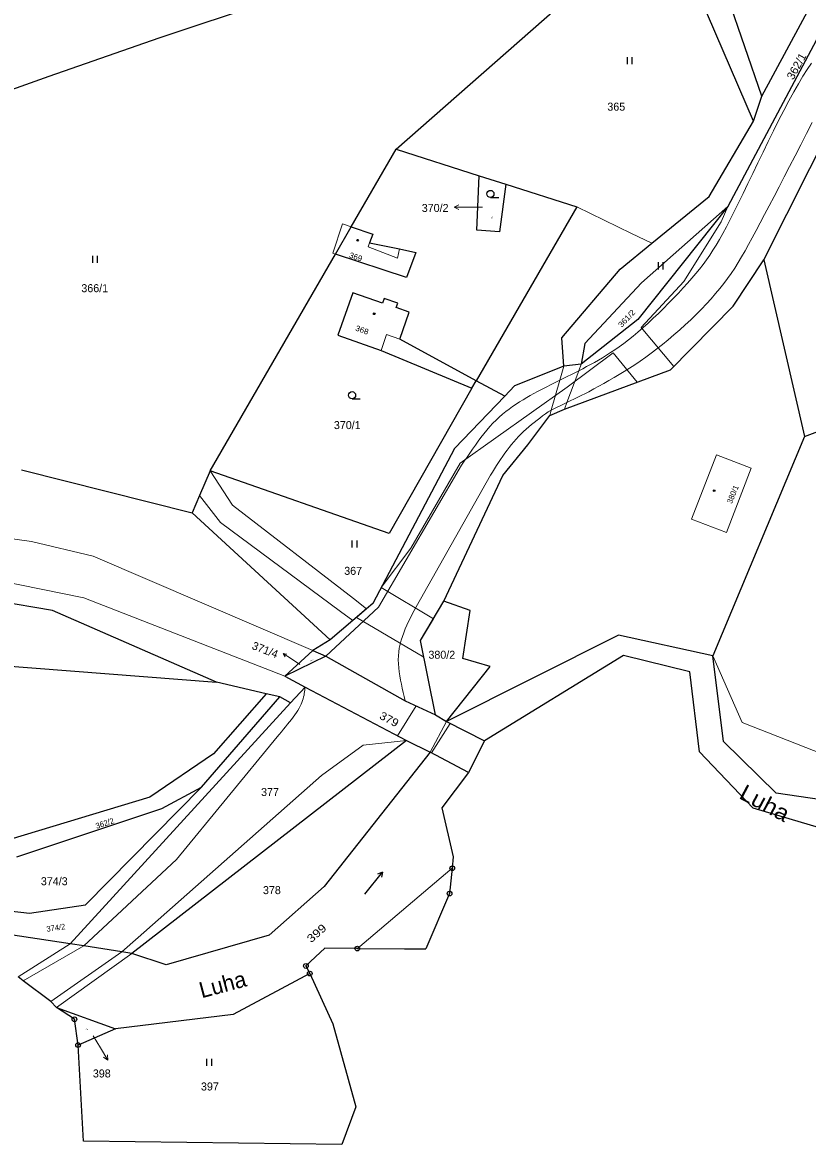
# Model space of a CAD drawing. Extents: x -504006 to -501322, y -1128098 to -1124665.
# Drawn here: x -502418.6 to -502251.7, y -1128098 to -1127859.7 of the extents above; entities that cross this region are included whole.
import ezdxf
from ezdxf.enums import TextEntityAlignment as Align

# ---------------------------------------------------------------- set-up
doc = ezdxf.new("R2010")
doc.units = 0
doc.header["$LTSCALE"] = 0.68
for name, color, linetype, lineweight in [('1', 7, 'Continuous', 25), ('13', 7, 'Continuous', 13), ('3', 7, 'Continuous', 25), ('4', 7, 'Continuous', 13), ('5', 7, 'Continuous', 25), ('7', 7, 'Continuous', 13), ('8', 7, 'Continuous', 25)]:
    doc.layers.add(name, color=color, linetype=linetype, lineweight=lineweight)
doc.layers.add('2', color=7, linetype='Continuous')

msp = doc.modelspace()

# ---------------------------------------------------------------- linework, layer by layer
at = {"layer": '1'}
for p, q in [((-502261.45, -1127875.35), (-502289.09, -1127795.08)), ((-502339.14, -1127886.6), (-502282.17, -1127836.5)), ((-502263.24, -1127880.61), (-502282.17, -1127836.5)), ((-502366.78, -1127855.42), (-502389.61, -1127863.03)), ((-502261.45, -1127875.35), (-502250.3, -1127854.66)), ((-502246.89, -1127857.93), (-502268.68, -1127898.79)), ((-502389.61, -1127863.03), (-502412.95, -1127871.18)), ((-502412.95, -1127871.18), (-502437.29, -1127879.78)), ((-502263.24, -1127880.61), (-502261.45, -1127875.35)), ((-502261.01, -1127910.1), (-502243.76, -1127875.74)), ((-502272.61, -1127896.66), (-502263.24, -1127880.61)), ((-502348.68, -1127903.07), (-502339.14, -1127886.6)), ((-502339.14, -1127886.6), (-502321.51, -1127892.23)), ((-502321.98, -1127903.78), (-502321.51, -1127892.23)), ((-502321.51, -1127892.23), (-502315.88, -1127894.03)), ((-502315.88, -1127894.03), (-502317.2, -1127904.16)), ((-502315.88, -1127894.03), (-502300.78, -1127898.86)), ((-502300.78, -1127898.86), (-502322.17, -1127935.76)), ((-502268.68, -1127898.79), (-502287.79, -1127922.8)), ((-502268.68, -1127898.79), (-502287.04, -1127914.99)), ((-502284.8, -1127906.58), (-502272.61, -1127896.66)), ((-502352.06, -1127908.9), (-502348.68, -1127903.07)), ((-502348.68, -1127903.07), (-502344.08, -1127904.66)), ((-502344.08, -1127904.66), (-502344.78, -1127906.51)), ((-502317.2, -1127904.16), (-502321.98, -1127903.78)), ((-502344.78, -1127906.51), (-502338.41, -1127907.77)), ((-502338.41, -1127907.77), (-502334.98, -1127908.5)), ((-502291.56, -1127912.08), (-502284.8, -1127906.58)), ((-502378.69, -1127954.88), (-502352.06, -1127908.9)), ((-502336.96, -1127913.85), (-502352.06, -1127908.9)), ((-502334.98, -1127908.5), (-502336.96, -1127913.85)), ((-502267.52, -1127919.9), (-502261.01, -1127910.1)), ((-502261.01, -1127910.1), (-502252.35, -1127947.59)), ((-502303.93, -1127926.63), (-502291.56, -1127912.08)), ((-502287.04, -1127914.99), (-502299.07, -1127927.86)), ((-502348.37, -1127917.07), (-502351.55, -1127926.1)), ((-502342.03, -1127919.31), (-502348.37, -1127917.07)), ((-502341.67, -1127918.29), (-502342.03, -1127919.31)), ((-502338.79, -1127919.31), (-502341.67, -1127918.29)), ((-502339.12, -1127920.25), (-502338.79, -1127919.31)), ((-502336.37, -1127921.22), (-502339.12, -1127920.25)), ((-502280.84, -1127933.48), (-502267.52, -1127919.9)), ((-502338.39, -1127926.96), (-502336.37, -1127921.22)), ((-502287.79, -1127922.8), (-502299.81, -1127932.26)), ((-502351.55, -1127926.1), (-502342.36, -1127929.34)), ((-502322.17, -1127935.76), (-502338.39, -1127926.96)), ((-502303.53, -1127932.65), (-502303.93, -1127926.63)), ((-502342.36, -1127929.34), (-502323.05, -1127937.35)), ((-502299.07, -1127927.86), (-502299.81, -1127932.26)), ((-502299.81, -1127932.26), (-502303.53, -1127932.65)), ((-502303.53, -1127932.65), (-502313.98, -1127936.85)), ((-502303.4, -1127941.78), (-502280.84, -1127933.48)), ((-502323.05, -1127937.35), (-502322.17, -1127935.76)), ((-502316.09, -1127939.05), (-502322.17, -1127935.76)), ((-502313.98, -1127936.85), (-502316.09, -1127939.05)), ((-502323.05, -1127937.35), (-502340.61, -1127968.24)), ((-502316.09, -1127939.05), (-502326.73, -1127950.16)), ((-502306.52, -1127943.16), (-502303.4, -1127941.78)), ((-502311.14, -1127949.39), (-502306.52, -1127943.16)), ((-502252.35, -1127947.59), (-502241.62, -1127943.56)), ((-502252.35, -1127947.59), (-502271.89, -1127994.18)), ((-502326.73, -1127950.16), (-502344.12, -1127983.08)), ((-502316.48, -1127955.93), (-502311.14, -1127949.39)), ((-502418.74, -1127954.72), (-502382.52, -1127963.86)), ((-502378.69, -1127954.88), (-502380.96, -1127960.17)), ((-502340.61, -1127968.24), (-502378.69, -1127954.88)), ((-502329, -1127982.59), (-502316.48, -1127955.93)), ((-502380.96, -1127960.17), (-502382.52, -1127963.86)), ((-502353.18, -1127990.79), (-502382.52, -1127963.86)), ((-502412.17, -1127984.56), (-502441.15, -1127979.72)), ((-502377.31, -1127999.77), (-502412.17, -1127984.56)), ((-502345.44, -1127984.21), (-502348.38, -1127986.7)), ((-502344.12, -1127983.08), (-502345.44, -1127984.21)), ((-502333.98, -1127990.98), (-502329, -1127982.59)), ((-502323.4, -1127984.6), (-502329, -1127982.59)), ((-502325, -1127994.8), (-502323.4, -1127984.6)), ((-502348.38, -1127986.7), (-502353.18, -1127990.79)), ((-502525.02, -1127988.48), (-502377.31, -1127999.77)), ((-502353.18, -1127990.79), (-502356.83, -1127993.06)), ((-502330.8, -1128006.76), (-502333.98, -1127990.98)), ((-502291.92, -1127989.81), (-502328.44, -1128008.18)), ((-502271.89, -1127994.18), (-502291.92, -1127989.81)), ((-502356.83, -1127993.06), (-502362.84, -1127998.54)), ((-502356.83, -1127993.06), (-502354.12, -1127994.27)), ((-502290.84, -1127994.17), (-502320.37, -1128012.27)), ((-502276.73, -1127997.64), (-502290.84, -1127994.17)), ((-502269.62, -1128012.41), (-502271.89, -1127994.18)), ((-502354.12, -1127994.27), (-502362.84, -1127998.54)), ((-502354.12, -1127994.27), (-502337.21, -1128003.75)), ((-502328.44, -1128008.18), (-502319.2, -1127996.5)), ((-502319.2, -1127996.5), (-502325, -1127994.8)), ((-502362.84, -1127998.54), (-502358.49, -1128000.84)), ((-502274.68, -1128014.62), (-502276.73, -1127997.64)), ((-502366.78, -1128002.26), (-502377.31, -1127999.77)), ((-502358.49, -1128000.84), (-502361.59, -1128004.22)), ((-502358.49, -1128000.84), (-502336.97, -1128012.2)), ((-502380.49, -1128022.11), (-502363.86, -1128002.95)), ((-502366.78, -1128002.26), (-502377.97, -1128015.05)), ((-502363.86, -1128002.95), (-502366.78, -1128002.26)), ((-502361.59, -1128004.22), (-502363.86, -1128002.95)), ((-502337.21, -1128003.75), (-502330.8, -1128006.76)), ((-502408.4, -1128055.35), (-502361.59, -1128004.22)), ((-502330.8, -1128006.76), (-502328.44, -1128008.18)), ((-502328.44, -1128008.18), (-502320.37, -1128012.27)), ((-502336.97, -1128012.2), (-502395.31, -1128057.42)), ((-502336.97, -1128012.2), (-502331.93, -1128014.67)), ((-502320.37, -1128012.27), (-502323.77, -1128018.99)), ((-502258.41, -1128023.41), (-502269.62, -1128012.41)), ((-502377.97, -1128015.05), (-502391.5, -1128024.2)), ((-502331.93, -1128014.67), (-502354.43, -1128043.24)), ((-502323.77, -1128018.99), (-502331.93, -1128014.67)), ((-502263.31, -1128026.56), (-502274.68, -1128014.62)), ((-502405.15, -1128047.13), (-502380.49, -1128022.11)), ((-502388.93, -1128026.65), (-502380.49, -1128022.11)), ((-502391.5, -1128024.2), (-502421.24, -1128033.24)), ((-502245.25, -1128025.33), (-502258.41, -1128023.41)), ((-502419.75, -1128036.93), (-502388.93, -1128026.65)), ((-502249.21, -1128030.75), (-502263.31, -1128026.56)), ((-502327.02, -1128036.92), (-502327.23, -1128039.33)), ((-502327.23, -1128039.33), (-502327.81, -1128044.72)), ((-502354.43, -1128043.24), (-502366.1, -1128053.55)), ((-502441.79, -1128046.07), (-502417.05, -1128048.89)), ((-502327.81, -1128044.72), (-502332.83, -1128056.43)), ((-502417.05, -1128048.89), (-502405.15, -1128047.13)), ((-502408.4, -1128055.35), (-502442.74, -1128050.19)), ((-502366.1, -1128053.55), (-502387.99, -1128059.81)), ((-502405.52, -1128055.8), (-502408.4, -1128055.35)), ((-502397.45, -1128057.08), (-502405.52, -1128055.8)), ((-502395.31, -1128057.42), (-502397.45, -1128057.08)), ((-502387.99, -1128059.81), (-502395.31, -1128057.42)), ((-502354.33, -1128056.27), (-502358.33, -1128060.09)), ((-502347.4, -1128056.4), (-502354.33, -1128056.27)), ((-502347.4, -1128056.4), (-502337.4, -1128056.44)), ((-502337.4, -1128056.44), (-502332.83, -1128056.43)), ((-502358.33, -1128060.09), (-502357.51, -1128061.7)), ((-502418.39, -1128063.21), (-502419.47, -1128062.4)), ((-502412.52, -1128067.62), (-502418.39, -1128063.21)), ((-502357.51, -1128061.7), (-502373.81, -1128070.41)), ((-502357.51, -1128061.7), (-502352.6, -1128072.39)), ((-502411.31, -1128068.88), (-502412.52, -1128067.62)), ((-502407.51, -1128071.41), (-502411.31, -1128068.88)), ((-502411.31, -1128068.88), (-502398.76, -1128073.44)), ((-502373.81, -1128070.41), (-502398.76, -1128073.44)), ((-502406.74, -1128076.89), (-502407.51, -1128071.41)), ((-502352.6, -1128072.39), (-502347.69, -1128089.99)), ((-502398.76, -1128073.44), (-502406.74, -1128076.89)), ((-502405.59, -1128097.3), (-502406.74, -1128076.89)), ((-502347.69, -1128089.99), (-502350.71, -1128098.02)), ((-502350.71, -1128098.02), (-502405.59, -1128097.3))]:
    msp.add_line(p, q, dxfattribs=at)
msp.add_lwpolyline([(-502323.77, -1128018.99), (-502329.42, -1128026.51), (-502327.02, -1128036.92)], dxfattribs=at)
at = {"layer": '13'}
for points in [[(-502268.68, -1127898.79), (-502287.79, -1127922.8), (-502299.81, -1127932.26), (-502303.53, -1127932.65), (-502313.98, -1127936.85), (-502316.09, -1127939.05), (-502326.73, -1127950.16), (-502342.35, -1127979.72), (-502336.01, -1127971.33), (-502325.56, -1127953.28), (-502302.83, -1127937.15), (-502293.06, -1127929.85), (-502287.94, -1127936.09), (-502280.84, -1127933.48), (-502280.14, -1127932.77), (-502287.06, -1127924.45), (-502278, -1127914.68), (-502270.12, -1127902)], [(-502344.12, -1127983.08), (-502345.44, -1127984.21), (-502347.59, -1127986.03), (-502333.27, -1127994.52), (-502333.98, -1127990.98), (-502331.21, -1127986.32), (-502342.35, -1127979.72)], [(-502334.88, -1128004.84), (-502338.9, -1128011.18), (-502336.97, -1128012.2), (-502334.07, -1128013.62), (-502331.93, -1128014.67), (-502331.62, -1128014.84), (-502327.65, -1128008.58), (-502328.44, -1128008.18), (-502330.8, -1128006.76)]]:
    msp.add_lwpolyline(points, close=True, dxfattribs=at)
at = {"layer": '3'}
for p, q in [((-502289.991, -1127868.51), (-502289.991, -1127867.01)), ((-502288.99, -1127868.51), (-502288.99, -1127867.01)), ((-502319.113, -1127896.83), (-502317.363, -1127896.83)), ((-502403.611, -1127910.75), (-502403.611, -1127909.25)), ((-502402.61, -1127910.75), (-502402.61, -1127909.25)), ((-502283.421, -1127912.11), (-502283.421, -1127910.61)), ((-502282.42, -1127912.11), (-502282.42, -1127910.61)), ((-502348.513, -1127939.59), (-502346.763, -1127939.59)), ((-502348.471, -1127971.19), (-502348.471, -1127969.69)), ((-502347.47, -1127971.19), (-502347.47, -1127969.69)), ((-502342.086, -1128040.138), (-502342.292, -1128041.216)), ((-502379.351, -1128081.3), (-502379.351, -1128079.8)), ((-502378.35, -1128081.3), (-502378.35, -1128079.8))]:
    msp.add_line(p, q, dxfattribs=at)
msp.add_lwpolyline([(-502345.78, -1128044.866), (-502342.086, -1128040.138), (-502343.082, -1128040.599)], dxfattribs=at)
for centre in [(-502319.1129, -1127896.0798), (-502348.5129, -1127938.8398)]:
    msp.add_circle(centre, 0.75, dxfattribs=at)
at = {"layer": '4'}
for p, q in [((-502300.78, -1127898.86), (-502289.13, -1127904.49)), ((-502352.63, -1127908.71), (-502350.54, -1127902.42)), ((-502350.54, -1127902.42), (-502348.68, -1127903.07)), ((-502289.13, -1127904.49), (-502284.8, -1127906.58)), ((-502344.78, -1127906.51), (-502345.11, -1127907.34)), ((-502345.11, -1127907.34), (-502338.83, -1127909.73)), ((-502338.83, -1127909.73), (-502338.41, -1127907.77)), ((-502352.06, -1127908.9), (-502352.63, -1127908.71)), ((-502341.17, -1127925.98), (-502342.36, -1127929.34)), ((-502338.39, -1127926.96), (-502341.17, -1127925.98)), ((-502299.81, -1127932.26), (-502300.33, -1127933.65)), ((-502303.53, -1127932.65), (-502304.39, -1127935.67)), ((-502304.39, -1127935.67), (-502300.33, -1127933.65)), ((-502300.33, -1127933.65), (-502302.88, -1127940.41)), ((-502300.33, -1127933.65), (-502299.49, -1127933.23)), ((-502309.12, -1127938.03), (-502304.39, -1127935.67)), ((-502304.39, -1127935.67), (-502306.2, -1127942.05)), ((-502298.21, -1127938.1), (-502302.88, -1127940.41)), ((-502302.88, -1127940.41), (-502306.2, -1127942.05)), ((-502302.88, -1127940.41), (-502303.4, -1127941.78)), ((-502306.2, -1127942.05), (-502306.86, -1127942.37)), ((-502306.2, -1127942.05), (-502306.52, -1127943.16)), ((-502342.9, -1127983.87), (-502325.24, -1127953.72)), ((-502276.37, -1127965.15), (-502271.06, -1127951.48)), ((-502271.06, -1127951.48), (-502263.68, -1127954.34)), ((-502378.69, -1127954.88), (-502373.93, -1127962.17)), ((-502319.11, -1127955.84), (-502334.89, -1127983.77)), ((-502263.68, -1127954.34), (-502268.98, -1127968.01)), ((-502376.49, -1127965.86), (-502380.96, -1127960.17)), ((-502373.93, -1127962.17), (-502348.22, -1127982.06)), ((-502268.98, -1127968.01), (-502276.37, -1127965.15)), ((-502351.01, -1127984.76), (-502376.49, -1127965.86)), ((-502428.27, -1127968.36), (-502416.65, -1127969.89)), ((-502416.65, -1127969.89), (-502403.51, -1127973.03)), ((-502403.51, -1127973.03), (-502356.83, -1127993.06)), ((-502405.51, -1127981.89), (-502431.19, -1127976.74)), ((-502362.84, -1127998.54), (-502405.51, -1127981.89)), ((-502348.22, -1127982.06), (-502345.44, -1127984.21)), ((-502354.12, -1127994.27), (-502342.9, -1127983.87)), ((-502348.38, -1127986.7), (-502351.01, -1127984.76)), ((-502271.89, -1127994.18), (-502265.62, -1128008.38)), ((-502328.44, -1128008.18), (-502331.93, -1128014.67)), ((-502265.62, -1128008.38), (-502244.31, -1128016.77)), ((-502364.47, -1128011.42), (-502385.8, -1128037.46)), ((-502346.16, -1128013.18), (-502355.03, -1128019.61)), ((-502336.97, -1128012.2), (-502346.16, -1128013.18)), ((-502355.03, -1128019.61), (-502393.97, -1128054.01)), ((-502385.8, -1128037.46), (-502398.47, -1128049.24)), ((-502347.4, -1128056.4), (-502327.23, -1128039.33)), ((-502398.47, -1128049.24), (-502405.52, -1128055.8)), ((-502408.4, -1128055.35), (-502419.47, -1128062.4)), ((-502418.39, -1128063.21), (-502405.52, -1128055.8)), ((-502393.97, -1128054.01), (-502397.45, -1128057.08)), ((-502397.45, -1128057.08), (-502412.52, -1128067.62)), ((-502411.31, -1128068.88), (-502395.31, -1128057.42))]:
    msp.add_line(p, q, dxfattribs=at)
for points in [[(-502299.49, -1127933.23), (-502298.669, -1127932.784), (-502297.836, -1127932.328), (-502297.007, -1127931.866), (-502296.169, -1127931.388), (-502295.311, -1127930.882), (-502294.448, -1127930.355), (-502293.569, -1127929.795), (-502292.659, -1127929.19), (-502291.738, -1127928.549), (-502290.791, -1127927.858), (-502289.805, -1127927.105), (-502288.8, -1127926.3), (-502287.763, -1127925.433), (-502286.688, -1127924.497), (-502285.607, -1127923.525), (-502284.516, -1127922.513), (-502283.41, -1127921.458), (-502282.322, -1127920.394), (-502281.248, -1127919.316), (-502280.181, -1127918.22), (-502279.156, -1127917.141), (-502278.168, -1127916.074), (-502277.212, -1127915.016), (-502276.32, -1127914), (-502275.485, -1127913.018), (-502274.69, -1127912.046), (-502273.943, -1127911.09), (-502273.227, -1127910.121), (-502272.521, -1127909.11), (-502271.832, -1127908.065), (-502271.142, -1127906.956), (-502270.432, -1127905.752), (-502269.709, -1127904.465), (-502268.955, -1127903.064), (-502268.149, -1127901.512), (-502267.3, -1127899.83), (-502266.392, -1127897.99), (-502265.419, -1127895.988), (-502264.412, -1127893.898), (-502263.369, -1127891.723), (-502262.284, -1127889.464), (-502261.193, -1127887.201), (-502260.09, -1127884.935), (-502258.971, -1127882.664), (-502257.872, -1127880.472), (-502256.786, -1127878.356), (-502255.711, -1127876.32), (-502254.68, -1127874.44), (-502253.687, -1127872.711), (-502252.718, -1127871.108), (-502251.795, -1127869.657), (-502250.901, -1127868.323)], [(-502250.744, -1127880.895), (-502251.966, -1127883.277), (-502253.174, -1127885.63), (-502254.377, -1127887.97), (-502255.541, -1127890.233), (-502256.677, -1127892.435), (-502257.793, -1127894.593), (-502258.856, -1127896.644), (-502259.877, -1127898.606), (-502260.861, -1127900.489), (-502261.78, -1127902.24), (-502262.644, -1127903.874), (-502263.471, -1127905.418), (-502264.25, -1127906.846), (-502265.001, -1127908.188), (-502265.744, -1127909.472), (-502266.471, -1127910.677), (-502267.2, -1127911.832), (-502267.951, -1127912.96), (-502268.716, -1127914.048), (-502269.514, -1127915.118), (-502270.366, -1127916.197), (-502271.26, -1127917.27), (-502272.214, -1127918.358), (-502273.237, -1127919.472), (-502274.297, -1127920.579), (-502275.4, -1127921.688), (-502276.551, -1127922.804), (-502277.717, -1127923.897), (-502278.905, -1127924.973), (-502280.121, -1127926.04), (-502281.331, -1127927.066), (-502282.541, -1127928.059), (-502283.759, -1127929.023), (-502284.95, -1127929.93), (-502286.122, -1127930.788), (-502287.289, -1127931.609), (-502288.425, -1127932.377), (-502289.546, -1127933.107), (-502290.667, -1127933.811), (-502291.763, -1127934.477), (-502292.849, -1127935.118), (-502293.939, -1127935.744), (-502295.009, -1127936.346), (-502296.075, -1127936.936), (-502297.15, -1127937.523), (-502298.21, -1127938.1)], [(-502325.24, -1127953.72), (-502324.664, -1127952.855), (-502324.08, -1127951.982), (-502323.5, -1127951.125), (-502322.917, -1127950.278), (-502322.321, -1127949.432), (-502321.726, -1127948.612), (-502321.123, -1127947.809), (-502320.503, -1127947.017), (-502319.881, -1127946.259), (-502319.246, -1127945.528), (-502318.591, -1127944.818), (-502317.93, -1127944.15), (-502317.253, -1127943.516), (-502316.554, -1127942.908), (-502315.851, -1127942.337), (-502315.135, -1127941.793), (-502314.401, -1127941.266), (-502313.666, -1127940.767), (-502312.923, -1127940.285), (-502312.165, -1127939.813), (-502311.41, -1127939.358), (-502310.652, -1127938.912), (-502309.882, -1127938.467), (-502309.12, -1127938.03)], [(-502306.86, -1127942.37), (-502307.451, -1127942.813), (-502308.048, -1127943.263), (-502308.635, -1127943.71), (-502309.22, -1127944.163), (-502309.806, -1127944.628), (-502310.38, -1127945.095), (-502310.947, -1127945.571), (-502311.512, -1127946.066), (-502312.062, -1127946.567), (-502312.601, -1127947.082), (-502313.135, -1127947.62), (-502313.65, -1127948.17), (-502314.152, -1127948.738), (-502314.647, -1127949.332), (-502315.124, -1127949.934), (-502315.591, -1127950.551), (-502316.055, -1127951.188), (-502316.505, -1127951.83), (-502316.948, -1127952.481), (-502317.39, -1127953.147), (-502317.823, -1127953.813), (-502318.252, -1127954.483), (-502318.684, -1127955.165), (-502319.11, -1127955.84)], [(-502334.89, -1127983.77), (-502335.303, -1127984.551), (-502335.717, -1127985.342), (-502336.116, -1127986.124), (-502336.503, -1127986.909), (-502336.876, -1127987.706), (-502337.223, -1127988.497), (-502337.544, -1127989.292), (-502337.837, -1127990.101), (-502338.091, -1127990.906), (-502338.306, -1127991.717), (-502338.478, -1127992.545), (-502338.6, -1127993.37), (-502338.671, -1127994.203), (-502338.693, -1127995.054), (-502338.671, -1127995.901), (-502338.609, -1127996.754), (-502338.511, -1127997.623), (-502338.383, -1127998.487), (-502338.229, -1127999.354), (-502338.05, -1128000.236), (-502337.856, -1128001.109), (-502337.649, -1128001.985), (-502337.43, -1128002.872), (-502337.21, -1128003.75)], [(-502358.49, -1128000.84), (-502358.526, -1128001.182), (-502358.565, -1128001.53), (-502358.61, -1128001.876), (-502358.663, -1128002.226), (-502358.729, -1128002.586), (-502358.809, -1128002.949), (-502358.907, -1128003.319), (-502359.027, -1128003.704), (-502359.169, -1128004.095), (-502359.338, -1128004.497), (-502359.539, -1128004.919), (-502359.77, -1128005.35), (-502360.035, -1128005.797), (-502360.337, -1128006.264), (-502360.664, -1128006.74), (-502361.019, -1128007.227), (-502361.401, -1128007.731), (-502361.799, -1128008.239), (-502362.216, -1128008.754), (-502362.652, -1128009.283), (-502363.095, -1128009.811), (-502363.546, -1128010.343), (-502364.009, -1128010.884), (-502364.47, -1128011.42)]]:
    msp.add_lwpolyline(points, dxfattribs=at)
at = {"layer": '5'}
for centre in [(-502347.3168, -1127905.9292), (-502343.8068, -1127921.5492), (-502271.5768, -1127959.1292)]:
    msp.add_circle(centre, 0.175, dxfattribs=at)
at = {"layer": '7'}
for p, q in [((-502326.821, -1127898.88), (-502325.82, -1127899.381)), ((-502363.162, -1127993.736), (-502362.765, -1127994.412)), ((-502400.414, -1128080.072), (-502400.501, -1128078.956))]:
    msp.add_line(p, q, dxfattribs=at)
for points in [[(-502320.82, -1127898.88), (-502323.82, -1127898.88), (-502326.821, -1127898.88), (-502325.82, -1127898.379)], [(-502359.65, -1127996.04), (-502361.4, -1127994.88), (-502363.162, -1127993.736), (-502362.383, -1127993.824)], [(-502403.51, -1128074.93), (-502401.96, -1128077.5), (-502400.414, -1128080.072), (-502401.359, -1128079.472)]]:
    msp.add_lwpolyline(points, dxfattribs=at)
at = {"layer": '8'}
for centre, radius in [((-502327.23, -1128039.3299), 0.5), ((-502327.23, -1128039.3299), 0.0303), ((-502327.81, -1128044.7199), 0.5), ((-502327.81, -1128044.7199), 0.0303), ((-502347.4, -1128056.3999), 0.5), ((-502347.4, -1128056.3999), 0.0303), ((-502358.33, -1128060.0899), 0.5), ((-502358.33, -1128060.0899), 0.0303), ((-502357.51, -1128061.6999), 0.5), ((-502357.51, -1128061.6999), 0.0303), ((-502407.51, -1128071.4099), 0.5), ((-502407.51, -1128071.4099), 0.0303), ((-502406.74, -1128076.8899), 0.5), ((-502406.74, -1128076.8899), 0.0303)]:
    msp.add_circle(centre, radius, dxfattribs=at)

# ---------------------------------------------------------------- texts
at = {"layer": '2'}
for s, height, rotation, width, p in [('362/1', 1.7, 61, 1.05, (-502253.3417, -1127869.3856)), ('369', 1.2, 341, 1.05, (-502347.9273, -1127910.0279)), ('361/2', 1.2, 47, 1.1, (-502289.7351, -1127922.9552)), ('368', 1.2, 340, 1.05, (-502346.5972, -1127925.5496)), ('371/4', 0.2, 25, 1.05, (-502357.0668, -1127995.2548)), ('379', 1.7, 332, 1.1, (-502341.0366, -1128008.4326)), ('399', 1.7, 41, 1.2, (-502355.4971, -1128053.7738)), ('398', 0.2, 338, 1.1, (-502404.9085, -1128073.6241))]:
    msp.add_text(s, height=height, rotation=rotation, dxfattribs=dict(at, width=width)).set_placement(p, align=Align.CENTER)
for s, p in [('365', (-502292.379, -1127878.405)), ('366/1', (-502403.2, -1127916.965)), ('370/1', (-502349.54, -1127946.045)), ('367', (-502348.289, -1127977.005)), ('380/2', (-502329.45, -1127994.825)), ('377', (-502365.959, -1128023.985)), ('374/3', (-502411.8, -1128042.935)), ('378', (-502365.559, -1128044.825)), ('397', (-502378.729, -1128086.535))]:
    msp.add_text(s, height=1.7, dxfattribs=at).set_placement(p, align=Align.CENTER)
msp.add_text('370/2', height=1.7, dxfattribs=at).set_placement((-502328.02, -1127899.922), align=Align.RIGHT)
for s, height, rotation, p in [('370/2', 0.2, 82, (-502318.6586, -1127901.1199)), ('380/1', 1.2, 68, (-502267.0648, -1127960.1273)), ('362/2', 1.2, 18, (-502400.8724, -1128030.3536)), ('374/2', 1.2, 8, (-502411.385, -1128052.5504))]:
    msp.add_text(s, height=height, rotation=rotation, dxfattribs=at).set_placement(p, align=Align.CENTER)
msp.add_text('371/4', height=1.7, rotation=339, dxfattribs=at).set_placement((-502364.6412, -1127994.7459), align=Align.RIGHT)
msp.add_text('398', height=1.7, dxfattribs=at).set_placement((-502403.6, -1128083.765))
at = {"layer": '7', "width": 1.1}
msp.add_text('Luha', height=3.4, rotation=332, dxfattribs=at).set_placement((-502261.6026, -1128026.9763), align=Align.CENTER)
at = {"layer": '7'}
msp.add_text('Luha', height=3.4, rotation=15, dxfattribs=at).set_placement((-502375.585, -1128065.6508), align=Align.CENTER)

doc.saveas('drawing.dxf')
